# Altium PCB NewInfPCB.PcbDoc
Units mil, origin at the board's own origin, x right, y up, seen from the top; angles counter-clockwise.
Board outline 2952.76 x 3787.4 mil, 2 copper layers (Top Layer, Bottom Layer); 62 components, 64 nets, 265 pads, 41 vias.
Unrouted connection lines stored in the file: 1.
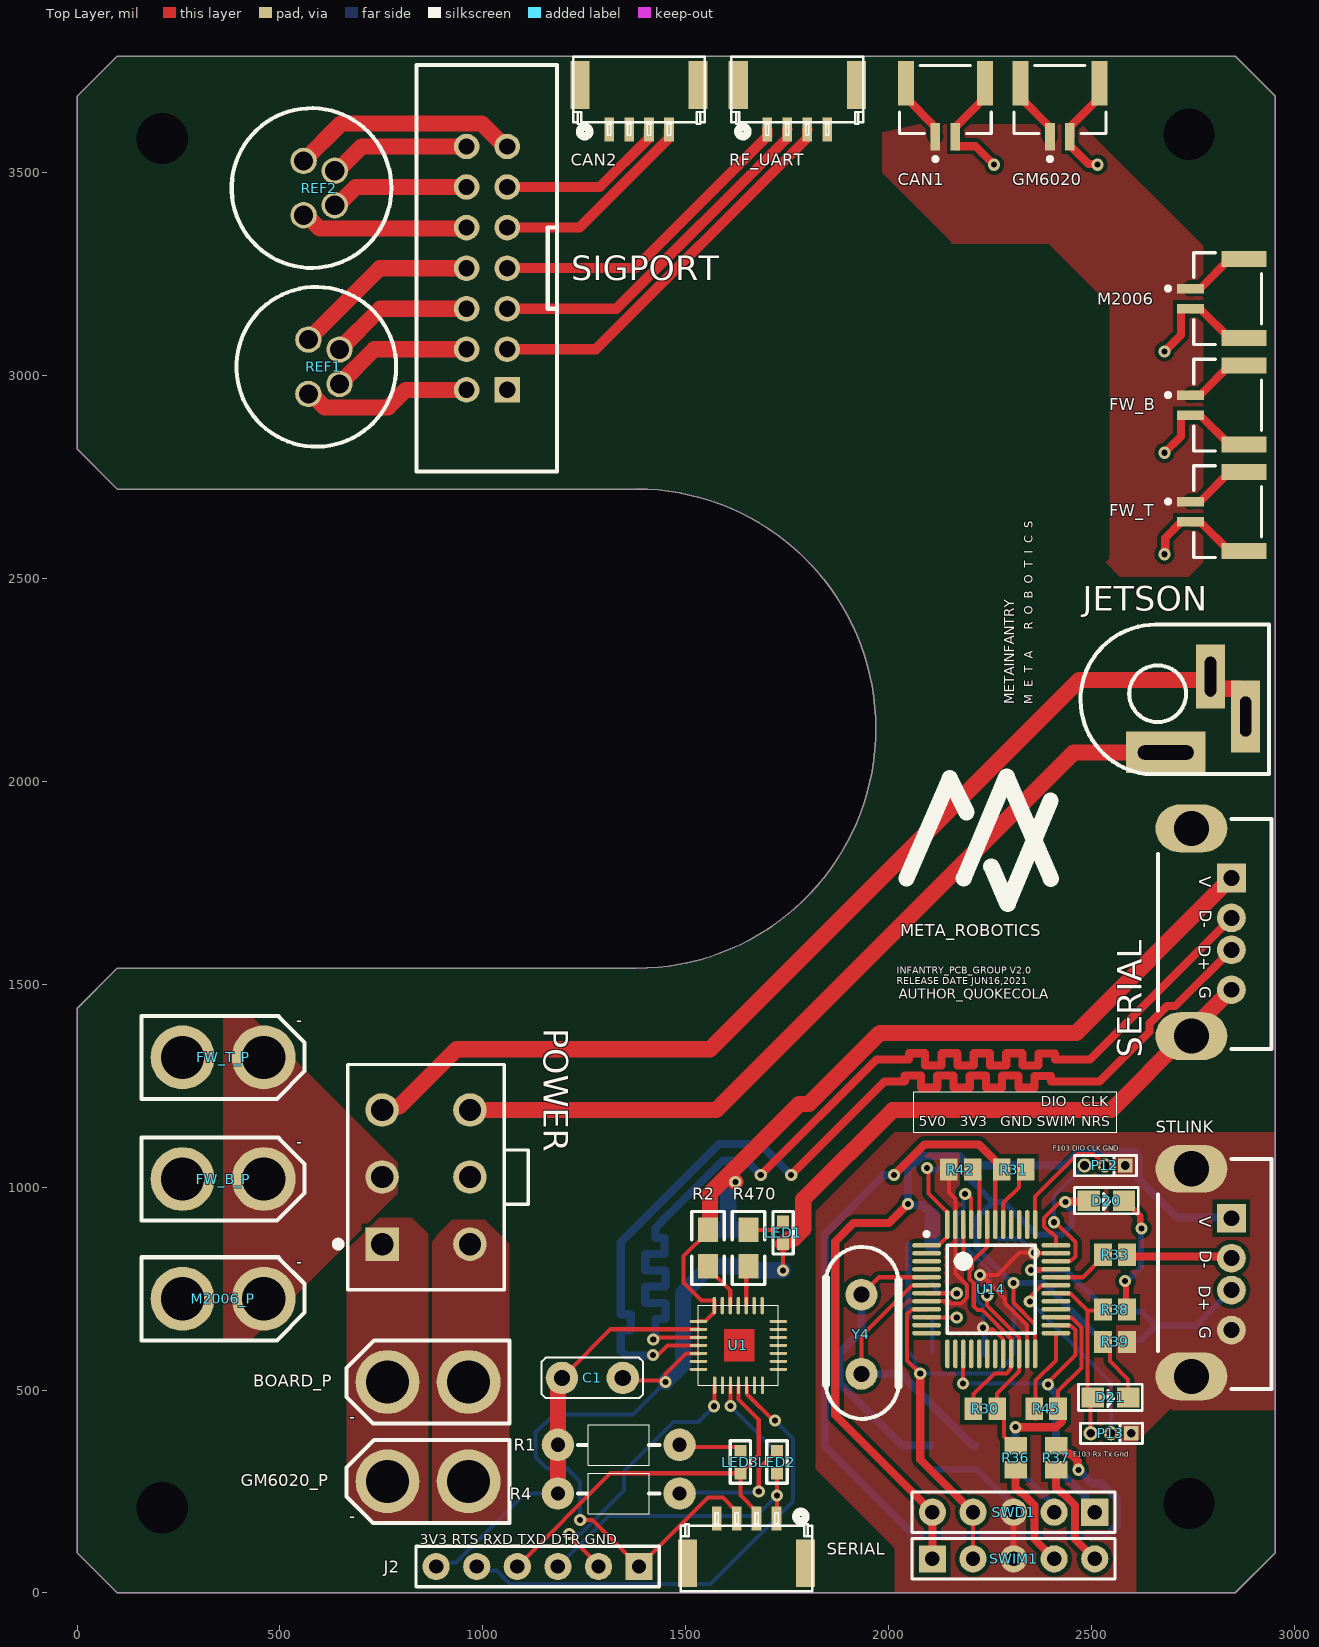
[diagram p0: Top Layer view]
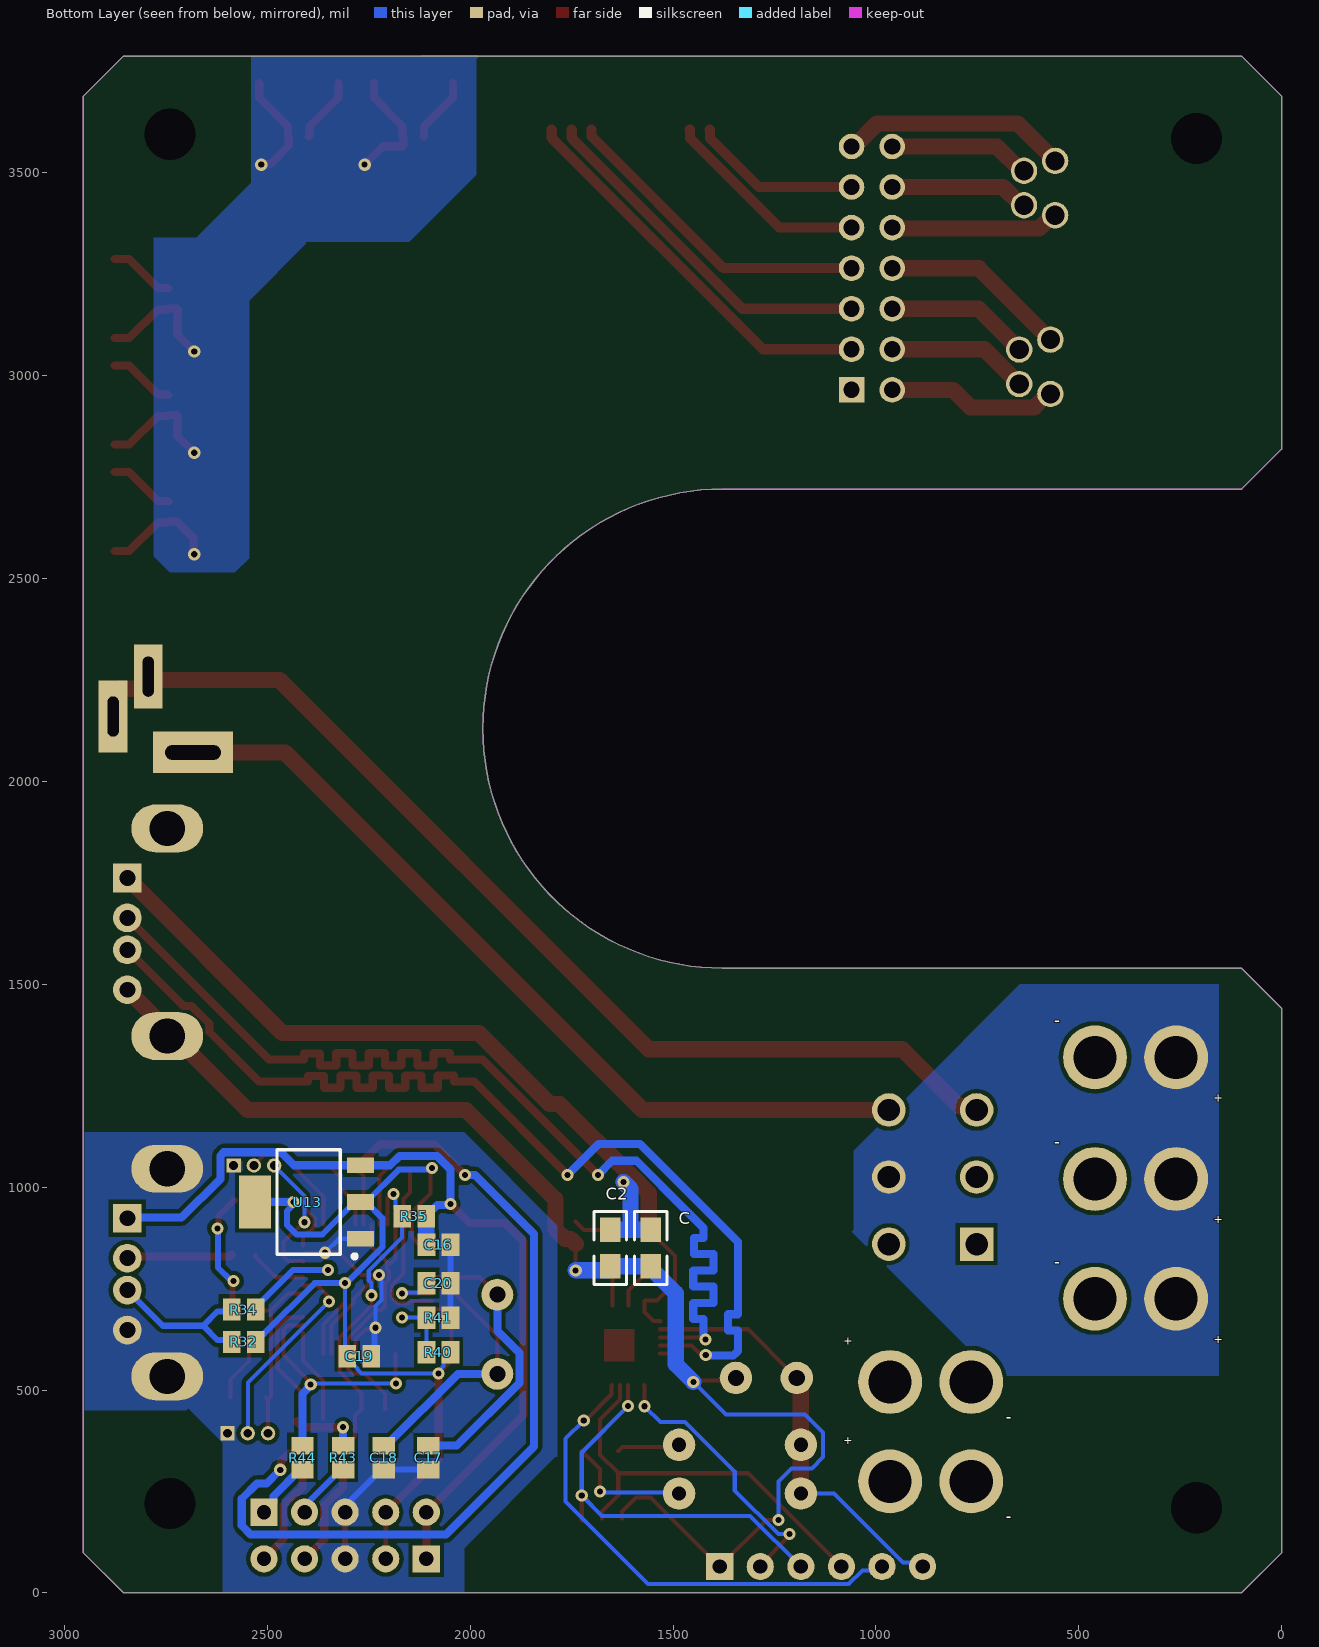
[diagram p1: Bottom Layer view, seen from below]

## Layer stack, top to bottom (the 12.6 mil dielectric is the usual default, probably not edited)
Top Solder: solder mask 0.4, Solder Resist, Dk 3.5
Top Layer: signal copper 1.4
Dielectric 1: dielectric 12.6, FR-4, Dk 4.8
Bottom Layer: signal copper 1.4
Bottom Solder: solder mask 0.4, Solder Resist, Dk 3.5

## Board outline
0.25,98.68 0.25,1441.19 98.68,1539.62 1378.2,1539.62 ccw(c1378.2,2130.17) 1378.2,2720.72 98.68,2720.72 0.25,2819.15 0.25,3689.23 98.68,3787.65 2854.58,3787.65 2953.01,3689.23 2953.01,98.68 2854.58,0.25 98.68,0.25

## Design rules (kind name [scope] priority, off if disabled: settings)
Clearance [All] p1: gap=10 ignorepadtopadclearanceinfootprint=FALSE except(0: Arc-Hole Track-Hole SMDPad-Text SMDPad-Hole THPad-Text THPad-Hole Via-Text Via-Hole Fill-Text Fill-Hole Poly-Text Poly-Hole Region-Text Region-Hole Text-Text Text-Hole; 5: Arc-Arc Arc-Track Arc-THPad Arc-Via Arc-Text Track-Track Track-THPad Track-Via Track-Text SMDPad-SMDPad SMDPad-THPad SMDPad-Via THPad-THPad THPad-Via Via-Via; 7.5: Arc-SMDPad Track-SMDPad)
PlaneConnect [All] p1: planeconnectstyle=Direct reliefexpansion=20 reliefentries=4 reliefconductorwidth=10 reliefairgap=10
PolygonConnect [All] p1: connectstyle=Direct reliefconductorwidth=10 reliefentries=4 polygonreliefangle="90 Angle" airgapwidth=10
RoutingVias [All] p1: holewidth=28 width=50 viastyle="Through Hole" minholewidth=28 minwidth=50 maxholewidth=28 maxwidth=50
SolderMaskExpansion [All] p1: expansion=4 istentingtop=FALSE
Width [All] p1: maxlimit=40 minlimit=10 preferedwidth=20 minimp=50.000000 maximp=50.000000 favimp=50.000000
29 further rules are at their usual default settings.

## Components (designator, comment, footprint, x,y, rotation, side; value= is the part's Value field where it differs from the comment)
BOARD_P "XT PLUGIN" XT30-M 865,520 r180 top
C "Cap" 0805 1555,895 r270 bottom value=0.1uF
C1 "4.7" 2P-150 1270,530 r0 top value=1uF
C2 "Cap" 0805 1655,895 r270 bottom value=1uF
C16 "Cap" C0805 2078.11,858.47 r0 bottom value=104
C17 "Cap" C0805 2103.11,333.46 r90 bottom value=22p
C18 "Cap" C0805 2213.11,333.46 r90 bottom value=22p
C19 "Cap" C0805 2273.11,583.47 r0 bottom value=104
C20 "Cap" C0805 2078.11,763.47 r0 bottom value=104
CAN1 "CAN1" JST-BM02B-GHS-TBT_V 2140,3655 r0 top
CAN2 "gh1.25_4p" GH1.25-LS-4P 1385,3705 r180 top
D20 "LED" 0805_LED 2533.11,963.47 r0 top
D21 "LED" 0805_LED 2543.11,478.46 r0 top
FW_B "CAN1" JST-BM02B-GHS-TBT_V 2810,2927.5 r270 top
FW_B_P "XT PLUGIN" XT30-M 360,1020 r0 top
FW_T "CAN1" JST-BM02B-GHS-TBT_V 2810,2665 r270 top
FW_T_P "XT PLUGIN" XT30-M 360,1320 r0 top
GM6020 "CAN1" JST-BM02B-GHS-TBT_V 2422.44,3655 r0 top
GM6020_P "XT PLUGIN" XT30-M 865,275 r180 top
J2 "" HDR2.54-LI-6P 1135,65 r180 top
JETSON "DC_PowerPort" DC-012 2683.15,2071.42 r90 top
LED1 "Res2" 0603 1740,860 r90 top value=1K
LED2 "Res2" 0603 1725,295 r90 top value=1K
LED3 "Res2" 0603 1635,295 r90 top value=1K
M2006 "CAN1" JST-BM02B-GHS-TBT_V 2810,3190 r270 top
M2006_P "XT PLUGIN" XT30-M 360,725 r0 top
P12 "ST-LINK" SIP3-1.27 2533.11,1053.46 r0 top
P13 "串口1" SIP3-1.27 2548.11,393.46 r0 top
POWER "64900621122" 64900621122 860,1025 r270 top
R1 "Res2" R 1335,365 r0 top value=1K
R2 "Res2" 0805 1555,895 r270 top value=1K
R4 "Res2" R 1335,245 r0 top value=1K
R30 "RES" C0805 2238.11,453.46 r0 top value=1k
R31 "RES" C0805 2308.11,1043.46 r180 top value=1k
R32 "RES" C0805 2558.11,618.47 r180 bottom value=1.5k
R33 "RES" C0805 2558.11,833.47 r180 top value=22
R34 "RES" C0805 2558.11,698.47 r180 bottom value=22
R35 "RES" C0805 2138.11,928.47 r0 bottom value=1.5k
R36 "RES" C0805 2313.11,332.99 r90 top value=22
R37 "RES" C0805 2413.11,333.46 r90 top value=22
R38 "RES" C0805 2558.11,698.47 r180 top value=1.5k
R39 "RES" C0805 2558.11,618.47 r180 top value=1.5k
R40 "RES" C0805 2078.11,593.47 r180 bottom value=4.7k
R41 "RES" C0805 2078.11,678.47 r0 bottom value=4.7k
R42 "RES" C0805 2178.11,1043.46 r0 top value=10k
R43 "RES" C0805 2313.11,333.46 r90 bottom value=22
R44 "RES" C0805 2413.11,333.46 r90 bottom value=22
R45 "RES" C0805 2388.11,453.46 r180 top value=100
R470 "Res2" 0805 1655,805 r90 top value=1K
REF1 "Referee_Air" "M8 CONNECTOR-LS" 589.68,3021.93 r270 top
REF2 "Referee_Air" "M8 CONNECTOR-LS" 577.91,3462.48 r270 top
RF_UART "gh1.25 P4" GH1.25-LS-4P 1775,3705 r180 top
SERIAL "gh1.25_4p" GH1.25-LS-4P 1650,85 r0 top
SERIAL "4 HEADER" USB-A/S_D 2845,1762.17 r270 top
SIGPORT "XH2.54 14PIN" DC-2.54-L-Z-14P 1010,3265 r90 top
STLINK "USB" USB-A/S_D 2845,923.43 r270 top
SWD1 "Head5" HDR2.54-LI-5P 2308.11,198.94 r180 top
SWIM1 "Header 5" HDR2.54-LI-5P 2308.11,83.94 r0 top
U1 "CP2102" CP2102 1630,610 r90 top
U13 "AMS1117-XX" SOT_223 2398.11,963.47 r90 bottom
U14 "STM32F103C8T6" LQFP48_N 2253.11,748.47 r0 top
Y4 "XTAL" XTAL_2 1934.48,624.92 r90 top

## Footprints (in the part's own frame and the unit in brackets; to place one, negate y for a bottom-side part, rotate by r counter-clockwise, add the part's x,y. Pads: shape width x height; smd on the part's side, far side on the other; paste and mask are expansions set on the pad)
2P-150 [mil]
  round 80 hole 40: 1(-75,0) 2(75,0)
  silkscreen extent -125,-50 125,50
0603 [mil]
  rect 30x30 smd: 1(0,0) 2(55,0)
  silkscreen extent -25,-25 80,25
0805 [mil]
  rect 60x50 smd: 1(0,0) 2(90,0)
  silkscreen extent -45,-40 135,40
0805_LED [mm]
  rect 1.4x1.27 smd: 1(-1.011,0.083) 2(1.199,0.083)
  silkscreen extent -1.9,-0.74 2.09,0.91
64900621122 [mm] "4.20mm Male Dual Row Vertical Header, 6p"
  rect 2.1x2.1 hole 1.4: 1(4.2,-2.75)
  round 2.1 hole 1.4: 2(0,-2.75) 3(-4.2,-2.75) 4(4.2,2.75) 5(0,2.75) 6(-4.2,2.75)
  silkscreen extent -7.05,-5.7 7.05,6.4, body extent -6.95,-4.8 7.25,6.3, height 12.82
C0805 [mm] "Chip Capacitor, Body 2.0x1.3mm, IPC High Density"
  rect 1.1x1.4 smd: 1(-0.75,0) 2(0.75,0)
  body extent -1.1,-0.72 1.1,0.72, height 1.4
CP2102 [mm]
  oval 0.2x1.1 smd: 1(-1.499,2.502) 2(-0.999,2.502) 3(-0.499,2.502) 4(0.001,2.502) 5(0.501,2.502) 6(1.001,2.502) 7(1.501,2.502) 15(1.499,-2.502) 16(0.999,-2.502) 17(0.499,-2.502) 18(-0.001,-2.502) 19(-0.501,-2.502) 20(-1.001,-2.502) 21(-1.501,-2.502)
  oval 1.1x0.2 smd: 8(2.489,1.511) 9(2.489,1.011) 10(2.489,0.511) 11(2.489,0.011) 12(2.489,-0.489) 13(2.489,-0.989) 14(2.489,-1.489) 22(-2.489,-1.511) 23(-2.489,-1.011) 24(-2.489,-0.511) 25(-2.489,-0.011) 26(-2.489,0.489) 27(-2.489,0.989) 28(-2.489,1.489)
  Top Layer region: -1.016,-1.016 1.016,-1.016 1.016,0.889 -1.016,0.889
  silkscreen extent -2.5,-2.5 2.5,2.5
DC-2.54-L-Z-14P [mm] "立式直插简牛插座，间距2.54 淘宝ID:黄晶宝石   店铺网址:https://shop463601444.taobao.com"
  rect 1.6x1.6 hole 1.02: 1(-7.62,-1.27)
  round 1.6 hole 1.02: 2(-7.62,1.27) 3(-5.08,-1.27) 4(-5.08,1.27) 5(-2.54,-1.27) 6(-2.54,1.27) 7(0,-1.27) 8(0,1.27) 9(2.54,-1.27) 10(2.54,1.27) 11(5.08,-1.27) 12(5.08,1.27) 13(7.62,-1.27) 14(7.62,1.27)
  silkscreen extent -12.72,-4.4 12.72,4.4, body extent -12.72,-4.4 12.71,4.7, height 8.8
DC-012 [mm] "5.5*2.1                  淘宝ID:黄晶宝石"
  rect 2.6x5 hole 0.9 slot 3.5 at 90 deg: 1(0,0)
  rect 4.5x1.8 hole 0.7 slot 2.5 at 0 deg: 2(2.25,-5)
  rect 4x1.8 hole 0.7 slot 2.5 at 0 deg: 3(4.75,-2.8)
  silkscreen extent -1.35,-6.48 8,5.33, body extent -1.11,-6.47 7.89,4.53, height 13.6
GH1.25-LS-4P [mm] "A1257WR-S-4P"
  rect 1.2x3 smd: 0(-3.7,-0.3) 0(3.7,-0.3)
  rect 0.6x1.5 smd: 1(1.875,2.5) 2(0.625,2.5) 3(-0.625,2.5) 4(-1.875,2.5)
  silkscreen extent -4.13,-2.05 4.12,2.93, body extent -4.12,-2.15 4.12,2.25, height 4.2
HDR2.54-LI-5P [mm] "排针，5脚"
  rect 1.7x1.7 hole 0.9: 1(-5.08,0)
  round 1.7 hole 0.9: 2(-2.54,0) 3(0,0) 4(2.54,0) 5(5.08,0)
  silkscreen extent -6.35,-1.27 6.35,1.27, body extent -6.35,-1.27 6.35,1.27, height 8.5
HDR2.54-LI-6P [mm] "排针，6脚"
  rect 1.7x1.7 hole 0.9: 1(-6.35,0)
  round 1.7 hole 0.9: 2(-3.81,0) 3(-1.27,0) 4(1.27,0) 5(3.81,0) 6(6.35,0)
  silkscreen extent -7.62,-1.27 7.62,1.27, body extent -7.62,-1.27 7.62,1.27, height 8.5
JST-BM02B-GHS-TBT_V [mm] "Connector, 2-Leads, Body 5.75x4.25mm, Pitch 1.25mm"
  rect 0.6x1.7 smd: 1(-0.625,-1.675) 2(0.625,-1.675)
  rect 1x2.8 smd: MP1(-2.475,1.675) MP2(2.475,1.675)
  silkscreen extent -2.88,-3.2 2.88,2.78, body extent -2.88,-2.17 2.87,2.78, height 4.21
LQFP48_N [mm] "Thin QFP, 48-Leads, Body 7x7mm, Pitch 0.5mm, IPC Medium Density"
  oval 1.8x0.3 smd: 1(-4.05,2.75) 2(-4.05,2.25) 3(-4.05,1.75) 4(-4.05,1.25) 5(-4.05,0.75) 6(-4.05,0.25) 7(-4.05,-0.25) 8(-4.05,-0.75) 9(-4.05,-1.25) 10(-4.05,-1.75) 11(-4.05,-2.25) 12(-4.05,-2.75) 25(4.05,-2.75) 26(4.05,-2.25) 27(4.05,-1.75) 28(4.05,-1.25) 29(4.05,-0.75) 30(4.05,-0.25) 31(4.05,0.25) 32(4.05,0.75) 33(4.05,1.25) 34(4.05,1.75) 35(4.05,2.25) 36(4.05,2.75)
  oval 0.3x1.8 smd: 13(-2.75,-4.05) 14(-2.25,-4.05) 15(-1.75,-4.05) 16(-1.25,-4.05) 17(-0.75,-4.05) 18(-0.25,-4.05) 19(0.25,-4.05) 20(0.75,-4.05) 21(1.25,-4.05) 22(1.75,-4.05) 23(2.25,-4.05) 24(2.75,-4.05) 37(2.75,4.05) 38(2.25,4.05) 39(1.75,4.05) 40(1.25,4.05) 41(0.75,4.05) 42(0.25,4.05) 43(-0.25,4.05) 44(-0.75,4.05) 45(-1.25,4.05) 46(-1.75,4.05) 47(-2.25,4.05) 48(-2.75,4.05)
  silkscreen extent -4.17,-2.75 2.75,3.57, body extent -3.5,-3.5 3.5,3.5, height 1.6
"M8 CONNECTOR-LS" [mm]
  round 1.65 hole 1.2: 0(-1.08,1.45) 1(1.08,1.45) 2(-1.7,-0.5) 3(1.7,-0.5)
  silkscreen extent -5,-5 5,5, body extent 0,0 0,0, height 19.1
R [mil]
  round 80 hole 35: 1(-150,0) 2(150,0)
  silkscreen extent -100,-50 100,50
SIP3-1.27 [mm]
  rect 0.9x0.9 hole 0.55: 1(1.27,0)
  round 0.9 hole 0.55: 2(0,0) 3(-1.27,0)
  silkscreen extent -1.91,-0.64 1.97,0.64
SOT_223 [mm]
  rect 1x1.7 smd: 1(-2.3,-3.25) 2(0,-3.25) 3(2.3,-3.25)
  rect 3.3x2 smd: 2(0,3.349)
  silkscreen extent -3.53,-3 3.28,1.98, body extent -3.25,-3.51 3.25,3.51, height 1.93
USB-A/S_D [mm] "A型直插母头，"
  oval 3x4.5 hole 2.2: 1(-3.1,-2.5) 1(9.9,-2.5)
  round 1.8 hole 1: 1(7,0) 2(4.5,0) 3(2.5,0)
  rect 1.8x1.8 hole 1: 4(0,0)
  silkscreen extent -3.7,-4.6 10.7,2.5, body extent -3.71,-4.6 10.69,2.5, height 14
XT30-M [mm]
  round 4 hole 2.7: 1(-2.54,0) 2(2.54,0)
  silkscreen extent -5.1,-2.6 5.11,2.6, body extent -5.18,-2.8 5.02,2.8, height 10.66
XTAL_2 [mm]
  round 2 hole 1: 1(-2.157,0.035) 2(2.796,0.035)
  silkscreen extent -4.98,-2.3 5.79,2.27, body extent -5.29,-2.36 6.06,2.29, height 3.5

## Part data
C C2: "Capacitor"
C1: library part "Cap Pol1", "Polarized Capacitor (Radial)"
CAN1 FW_B FW_T GM6020 M2006: library part CMP-2000-05957-1, "Disconnectable Crimp Style Connector, Pitch 1.25 mm, 1 x 2 Position, Height 4.05 mm, -25 to 85 degC, RoHS, Tape and Reel", Color=Natural, Manufacturer=JST-Sales-America-Inc., Package Description="Disconnectable Crimp Style Connector, Pitch 1.25 mm, 1 x 2 Position, Height 4.05 mm", Package Reference=BM02B-GHS-TBT
J2: library part CON6, "Connector"
LED1 LED2 LED3 R1 R2 R4 R470: "Resistor"
P12 P13: library part "Header 3", "Header, 3-Pin"
POWER: library part CMP-1502-00495-1, "THT Male Header WR-MPC4, Vertical, Dual Row, pitch 4.2 mm, 6 pins", Contact Resistance=10mOhm, Manufacturer="Wurth Elektronik", Operating Temperature=-40to105degC, Working Voltage=600VAC
SERIAL: "4 Pin Header"
STLINK: library part USB_G
SWD1: library part "HEAD 5"
SWIM1: "Header, 5-Pin"
U1: library part Component_2
U13: "AMS   800mA LOW DROPOUT VOLTAGE REGULATOR"
U14: "STM32 ARM-based 32-bit MCU with 64 Kbytes Flash, 48-pin LQFP, Industrial Temperature"

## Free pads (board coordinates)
  round 0 hole 125.98: ""(210,210) ""(210,3585) ""(2740,220) ""(2740,3595)

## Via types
v1: diameter 30, hole 15, Top Layer to Bottom Layer, 41 vias

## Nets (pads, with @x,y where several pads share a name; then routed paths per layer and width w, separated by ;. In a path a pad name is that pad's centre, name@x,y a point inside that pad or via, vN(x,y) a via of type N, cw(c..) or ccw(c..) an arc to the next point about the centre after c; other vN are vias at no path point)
3.3: C1.1 J2.6 R1.1 R4.1 U1.6 | length 1061.8
  Top Layer w10: C1.1@1185,540 1205,540 1314.87,649.87 1531.06,649.87 U1.6
  Top Layer w40: R4.1 R1.1 C1.1@1185,540
  Bottom Layer w10: J2.6 894.93,74.93 933.46,74.93 1103.53,245 R4.1
3V3: C19.2 D20.1 R32.2 R40.2 SWD1.4 SWIM1.2 U13.2 U14.1 U14.9 U14.24 U14.36 U14.48 | length 3006.1
  Top Layer w10: v1(2078.11,540.75) 2045.73,573.13 2045.73,687.19 2057.44,698.91 2093.31,698.91 U14.9 ; U14.1 2123.19,856.73 2144.84,878.39 U14.48 2144.84,937.44 2098.11,984.17 2098.11,1043.46 v1(2094.39,1047.18) ; SWIM1.2 SWD1.4 ; v1(2308.11,763.47) 2308.11,715.18 2361.37,661.91 U14.24 ; U14.36 2412.55,877.64 2401.73,888.47 2397.75,888.47 2383.11,903.11 2383.11,923.82 2418.92,959.64 2431.78,959.64 v1(2435.61,963.47)
  Top Layer w20: v1(2078.11,540.75) 2078.11,328.94 SWD1.4 ; v1(2435.61,963.47) 2437.24,965.1 2491.66,965.1 D20.1
  Bottom Layer w10: R40.2 2065.23,576.81 2065.23,559.03 2078.11,546.16 v1(2078.11,540.75) 2267.75,540.75 2277.73,550.73 2277.73,552.66 2302.63,577.56 C19.2 2308.11,588.94 v1(2308.11,763.47)
  Bottom Layer w15: v1(2094.39,1047.18) 2098.11,1043.46 2176.38,1043.46 U13.2@2256.38,963.47 ; v1(2435.61,963.47) 2435.61,956.91 2451.89,940.62 2451.89,907.25 2428.11,883.47 2363.93,883.47 2283.93,963.47 2270.15,963.47 U13.2@2256.38,963.47 ; R32.2 2528.58,624.37 2514.43,638.52 2508.52,638.52 2383.58,763.47 v1(2308.11,763.47) 2305.24,763.47 2216.38,852.33 2216.38,923.47 U13.2@2256.38,963.47
  Bottom Layer w20: v1(2435.61,963.47) U13.2@2529.95,963.47
5V0: C16.2 R35.1 STLINK.4 SWD1.5 SWIM1.1 U13.3 | length 2265.8
  Top Layer w20: v1(2048.11,958.47) 2000.91,911.27 1914.02,911.27 1868.74,865.99 1868.74,438.31 SWD1.5 SWIM1.1
  Bottom Layer w20: R35.1 2108.58,934.37 2096.93,946.02 2091.02,946.02 2080.49,956.55 2050.02,956.55 v1(2048.11,958.47) 2048.11,1043.32 2081.97,1077.18 2174.48,1077.18 2197.64,1054.02 U13.3 2434.25,1054.02 2466.41,1086.18 2608.11,1086.18 2608.11,1085.11 2615.82,1077.39 2615.82,1020.36 2711.18,925 2843.43,925 STLINK.4
  Bottom Layer w40: C16.2 2108.11,858.94 2108.11,927.99 R35.1
(NRS): R37.1 SWIM1.5 | length 261.3
  Top Layer w20: R37.1 2413.11,259.12 2424.82,247.4 2428.18,247.4 2459.64,215.94 2459.64,132.4 SWIM1.5
(SWCLK): R44.1 SWD1.1 | length 147.8
  Bottom Layer w20: R44.1 2419.01,303.94 2484.64,238.31 2484.64,222.4 SWD1.1
(SWDIO): R43.1 SWD1.2 | length 147.8
  Bottom Layer w15: R43.1 2319.01,303.94 2398.17,224.78 2398.17,208.87 SWD1.2
(SWIM): R36.1 SWIM1.4 | length 260.8
  Top Layer w20: R36.1 2313.11,259.12 2324.82,247.4 2328.18,247.4 2359.64,215.94 2359.64,132.4 SWIM1.4
AMMO_DC: FW_B_P.1 FW_T_P.1 M2006_P.1 POWER.5
AMMO_GND: FW_B_P.2 FW_T_P.2 M2006_P.2 POWER.2
BOOT0: R42.2 U14.44 | length 142.2
  Top Layer w10: R42.2 2223.58,1027.52 U14.44
CAN1_H: CAN1.2 CAN1.MP2 FW_B.2 FW_B.MP2 FW_T.2 FW_T.MP2 GM6020.2 GM6020.MP2 M2006.2 M2006.MP2 | length 1452.5
  Top Layer w20: CAN1.MP2 2237.44,3685.51 2166.42,3614.49 2166.42,3590.87 CAN1.2 2164.61,3567.4 2166.42,3565.59 2214.41,3565.59 v1(2260,3520) ; v1(2515,3520) 2513.09,3521.91 2492.54,3521.91 2447.05,3567.4 GM6020.2 2448.86,3590.87 2448.86,3614.49 2519.88,3685.51 GM6020.MP2 ; v1(2680,2560) 2681.91,2561.91 2681.91,2599.91 2722.4,2640.39 FW_T.2 2745.87,2638.58 2769.49,2638.58 2840.51,2567.56 FW_T.MP2 ; v1(2680,2810) 2720.59,2850.59 2720.59,2901.08 2722.4,2902.89 FW_B.2 2745.87,2901.08 2769.49,2901.08 2840.51,2830.06 FW_B.MP2 ; v1(2680,3060) 2720.59,3100.59 2720.59,3163.58 2722.4,3165.39 M2006.2 2745.87,3163.58 2769.49,3163.58 2840.51,3092.56 M2006.MP2
CAN1_L: CAN1.1 CAN1.MP1 FW_B.1 FW_B.MP1 FW_T.1 FW_T.MP1 GM6020.1 GM6020.MP1 M2006.1 M2006.MP1 | length 810.3
  Top Layer w20: CAN1.MP1 2042.56,3685.51 2113.58,3614.49 2113.58,3590.87 CAN1.1 ; GM6020.MP1 2325,3685.51 2396.02,3614.49 2396.02,3590.87 GM6020.1 ; FW_T.1 2745.87,2691.42 2769.49,2691.42 2840.51,2762.44 FW_T.MP1 ; FW_B.1 2745.87,2953.92 2769.49,2953.92 2840.51,3024.94 FW_B.MP1 ; M2006.1 2745.87,3216.42 2769.49,3216.42 2840.51,3287.44 M2006.MP1
CAN2_H: CAN2.3 SIGPORT.11 | length 420.2
  Top Layer w25: SIGPORT.11 1288.44,3465 1408.92,3585.48 1408.92,3605.89 CAN2.3
CAN2_L: CAN2.4 SIGPORT.9 | length 510.8
  Top Layer w25: SIGPORT.9 1237.65,3365 1458.13,3585.48 1458.13,3605.89 CAN2.4
D+: SERIAL.2@2845,1585 U1.4 | length 2672.4
  Top Layer w10: v1(1419.31,586.16) 1423.84,586.16 1425,585 1430,585 1455.06,610.06 U1.4
  Top Layer w20: v1(1760,1030) 1990,1260 2030,1260 2040,1260 2040,1275 2080,1275 2080,1245 2120,1245 2120,1275 2160,1275 2160,1245 2200,1245 2200,1275 2240,1275 2240,1245 2280,1245 2280,1275 2320,1275 2320,1245 2360,1245 2360,1274.09 2400,1274.09 2400,1260 2520,1260 2540,1280 2642.99,1382.99 2642.99,1403.08 2686.37,1446.46 2706.46,1446.46 SERIAL.2@2845,1585
  Bottom Layer w20: v1(1419.31,586.16) 1419.31,585 1351.72,585 1345,591.72 1340,596.72 1340,646.72 1364.52,646.72 1364.52,686.72 1340,686.72 1340,865 1355,880 1581.72,1106.72 1683.28,1106.72 v1(1760,1030)
D-: SERIAL.3@2845,1663.74 U1.5 | length 2672.9
  Top Layer w10: v1(1420.11,624.87) 1425.28,624.87 1430.15,629.74 U1.5
  Top Layer w20: v1(1685,1030) 1970,1315 2040,1315 2050,1315 2050,1330 2090,1330 2090,1300 2130,1300 2130,1330 2170,1330 2170,1300 2210,1300 2210,1330 2250,1330 2250,1300 2290,1300 2290,1330 2330,1330 2330,1300 2370,1300 2370,1329.34 2410,1329.34 2410,1315 2490,1315 2496.26,1315 SERIAL.3@2845,1663.74
  Bottom Layer w20: v1(1420.11,624.87) 1425.28,624.87 1425.28,674.87 1450.28,674.87 1450.28,714.87 1400.28,714.87 1400.28,754.87 1450.28,754.87 1450.28,794.87 1400.28,794.87 1400.28,834.87 1448.06,834.87 1448.06,874.87 1425.28,874.87 1425.28,899.78 1455.5,930 1470.5,945 1590.5,1065 1650,1065 v1(1685,1030)
DTR: J2.2 U1.28 | length 676.9
  Top Layer w10: v1(1212.98,145) 1212.98,141.01 1285,68.99 J2.2 ; v1(1570,460) 1570.69,460.69 1570.69,511.31 U1.28
  Bottom Layer w10: v1(1212.98,145) 1240.36,145 1347.97,252.62 1347.97,298.68 1470.23,420.94 1530.94,420.94 v1(1570,460)
GMB_DC: BOARD_P.1 GM6020_P.1 POWER.4
GMB_GND: BOARD_P.2 GM6020_P.2 POWER.1
GND: C1.2 C2.2 C.2 J2.1 LED1.1 SERIAL.1@2746.57,1372.4 SERIAL.1@2746.57,1884.21 SERIAL.1@2845,1486.57 SERIAL.3@1625.39,183.43 U1.3 | length 3421.3
  Top Layer w10: v1(1240,180) 1270,180 J2.1 1555,235 1591.54,235 1625.39,201.14 SERIAL.3@1625.39,183.43 ; C1.2 1351.17,523.83 1446.17,523.83 v1(1450,520) 1450,539.23 1500.96,590.19 1531.32,590.19 U1.3 ; v1(1740,795) LED1.1
  Top Layer w40: LED1.1 1752.5,872.5 1766.39,872.5 1790,896.11 1790,970 2010,1190 2548.43,1190 2734.02,1375.59 SERIAL.1@2845,1486.57
  Bottom Layer w10: v1(1240,180) 1240,275 1208.09,306.91 1158.09,306.91 1130,335 1130,395 1175,440 1370,440 v1(1450,520)
  Bottom Layer w40: v1(1450,520) 1493.43,563.43 1493.43,738.43 1555,800 C.2 C2.2 1655,800 1660,795 v1(1740,795)
GNDG: C16.1 C17.1 C18.1 C19.1 C20.1 P12.1 P13.1 R39.1 R41.1 R42.1 STLINK.1 SWD1.3 SWIM1.3 U13.1 U14.8 U14.20 U14.23 U14.35 U14.47 | length 1859.5
  Top Layer w10: U14.8 2148.33,718.94 2153.81,713.47 2178.46,713.47 2193.11,728.11 2193.11,758.79 2164.52,787.37 U14.47 2164.52,971.45 2148.58,987.39 R42.1 ; v1(2225,783.47) v1@2228.46,783.47 ; v1(2233.11,653.47) 2236.93,649.64 2257.88,649.64 2282.29,625.23 2282.29,589.36 U14.20 ; U14.23 2341.69,660.38 2287.48,714.6 2287.48,724.45 v1@2228.46,783.47 ; U14.35 2412.21,837.39 2359.18,837.39 v1(2358.11,838.47) 2323.11,838.47 2268.11,783.47 v1@2228.46,783.47
  Top Layer w15: SWIM1.3 SWD1.3
  Bottom Layer w10: v1(2225,783.47) 2225,778.05 2218.11,771.16 2218.11,722.52 2233.11,707.52 v1(2233.11,653.47) ; U13.1 2323.66,872.91 v1(2358.11,838.47)
  Bottom Layer w15: R41.1 C20.1 C16.1 ; C17.1 C18.1 2219.01,303.94 2298.17,224.78 2298.17,208.87 SWD1.3 ; v1(2233.11,653.47) 2235.98,650.6 2235.98,591.07 C19.1
MPC_DC: JETSON.1 POWER.6 | length 2079.8
  Top Layer w40: POWER.6 1575.35,1190.35 2456.42,2071.42 JETSON.1
MPC_GND: JETSON.2 JETSON.3 POWER.3 | length 2635.6
  Top Layer w40: POWER.3 759.9,1198.52 793.52,1198.52 935,1340 1560,1340 2470,2250 2784.96,2250 2806.38,2228.58 2864.57,2228.58 2880,2213.15 JETSON.2
NetC20_2: C20.2 U14.7 | length 148.8
  Top Layer w10: U14.7 2093.74,738.54 2168.03,738.54 v1(2168.11,738.47)
  Bottom Layer w10: C20.2 2107.63,757.56 2124.29,740.91 2165.67,740.91 v1(2168.11,738.47)
NetD20_2: D20.2 R38.1 | length 328.4
  Top Layer w15: D20.2@2582.04,968.47 D20.2 2582.86,966.73 2620.24,929.35 2620.24,901.34 v1(2623.11,898.47) ; v1(2583.11,768.47) 2585.37,766.2 2585.37,700.73 R38.1 2592.63,693.47 R38.1@2602.63,703.47
  Bottom Layer w15: v1@2588.11,768.47 2621.67,802.03 v1@2621.67,899.9
NetD21_2: D21.2 R39.2 | length 162.3
  Top Layer w10: R39.2 2545.23,601.81 2545.23,571.35 2590.3,526.28 D21.2
NetLED1_2: LED1.2 R470.2 | length 93.3
  Top Layer w10: R470.2 1720,895 LED1.2
NetLED2_2: LED2.2 R4.2 | length 315.7
  Top Layer w10: v1(1680,250) 1680,305 LED2.2
  Bottom Layer w10: R4.2 1487.5,247.5 1677.5,247.5 v1(1680,250)
NetLED3_2: LED3.2 R1.2 | length 156.2
  Top Layer w10: R1.2 1490,360 1625,360 LED3.2
NetR2_2: R2.2 U1.10 | length 119.7
  Top Layer w10: R2.2 1555,800 1609.87,745.13 U1.10
NetR32_1: R32.1 R34.1 STLINK.2 | length 383.5
  Bottom Layer w15: R32.1@2592.53,623.36 2623,623.36 2658.11,658.47 ; R34.1@2592.53,693.57 2623,693.57 2658.11,658.47 ; STLINK.2 2757.21,658.47 2658.11,658.47
NetR33_1: R33.1 STLINK.3 | length 260.9
  Top Layer w20: R33.1 2591.87,829.23 2840.77,829.23 STLINK.3
NetR40_1: R40.1 R41.2 U14.10 | length 220.4
  Top Layer w10: U14.10 2094.01,679.22 2167.35,679.22 v1(2168.11,678.47)
  Bottom Layer w10: R40.1 R41.2 v1(2168.11,678.47)
OS_IN: C17.2 U14.5 Y4.2 | length 706.8
  Top Layer w10: Y4.2 1976.1,777.99 U14.5
  Bottom Layer w20: Y4.2 1933.11,645.48 1878.74,591.11 1878.74,517.48 2033.22,362.99 C17.2
OS_OUT: C18.2 U14.6 Y4.1 | length 659.1
  Top Layer w10: Y4.1 1933.11,633.63 2057.44,757.96 2093.31,757.96 U14.6
  Bottom Layer w20: Y4.1 2030.19,540 2207.2,362.99 C18.2
REFEREE_A1: REF1.0 SIGPORT.6 | length 354.9
  Top Layer w40: REF1.0 747.32,3165 SIGPORT.6
REFEREE_A2: REF1.1 SIGPORT.4 | length 348.7
  Top Layer w40: REF1.1 732.36,3065 SIGPORT.4
REFEREE_A3: REF1.2 SIGPORT.8 | length 463
  Top Layer w40: REF1.2 746.14,3265 SIGPORT.8
REFEREE_A4: REF1.3 SIGPORT.2 | length 421.5
  Top Layer w40: REF1.3 576.75,2955 609.83,2921.93 766.83,2921.93 809.91,2965 SIGPORT.2
REFEREE_B1: REF2.0 SIGPORT.14 | length 349.9
  Top Layer w40: REF2.0 641.75,3505 701.75,3565 SIGPORT.14
REFEREE_B2: REF2.1 SIGPORT.12 | length 343.7
  Top Layer w40: REF2.1 641.75,3419.96 686.79,3465 SIGPORT.12
REFEREE_B3: REF2.2 SIGPORT.13 | length 563.3
  Top Layer w40: REF2.2 650.32,3621.5 997.28,3621.5 1053.78,3565 SIGPORT.13
REFEREE_B4: REF2.3 SIGPORT.10 | length 416.5
  Top Layer w40: REF2.3 564.98,3395.55 598.05,3362.48 957.48,3362.48 SIGPORT.10
RTS: J2.5 U1.24 | length 1219.3
  Top Layer w10: U1.24 1651.19,510.94 1651.19,489.66 1715.85,425 v1(1720,425)
  Bottom Layer w10: J2.5 994.93,55.07 1033.46,55.07 1067,21.54 1561.54,21.54 1765,225 1765,380 v1(1720,425)
RX: D21.1 P13.3 R38.2 U14.30 | length 437.7
  Top Layer w10: U14.30 2412.9,738.28 2448.77,738.28 2490.49,696.56 ; D21.1@2490.49,483.46 2490.49,696.56 ; P13.3 2498.11,476.54 D21.1 ; R38.2 2526.67,696.56 2490.49,696.56
RXD: J2.4 LED3.1 SERIAL.2@1674.61,183.43 U1.25 | length 1029.4
  Top Layer w10: J2.4 1315,295 LED3.1 ; U1.25 1630.44,476.43 1680,426.87 1680,340 LED3.1 ; SERIAL.2@1674.61,183.43 1674.61,201.14 1635,240.75 LED3.1
SUS: R470.1 U1.12 | length 99.4
  Top Layer w10: U1.12 1649.24,799.24 R470.1
SWCLK1: P12.2 U14.37 | length 295.3
  Top Layer w10: U14.37 2361.37,976.73 2465.82,1081.18 2505.39,1081.18 P12.2
SWDIO1: P12.3 U14.34 | length 331.7
  Top Layer w10: v1(2408.11,913.47) 2411.38,913.47 2460.49,864.36 2460.49,829.42 2448.77,817.71 2412.9,817.71 U14.34
  Bottom Layer w10: v1(2408.11,913.47) 2408.11,978.47 P12.3
SWIM: R30.2 R35.2 R36.2 U14.22 U14.45 | length 828.5
  Top Layer w10: v1(2188.88,983.47) 2193.11,983.47 2203.55,973.02 2203.55,908.26 U14.45 ; v1(2243.11,733.47) 2243.11,708.47 2321.66,629.91 2321.66,589.36 U14.22 2322,545.5 2267.63,491.13 R30.2 2284.29,436.81 2284.29,385.43 2307.2,362.52 R36.2
  Bottom Layer w10: v1(2188.88,983.47) 2188.88,978.05 2184.29,973.47 2184.29,945.12 R35.2 2167.63,876.19 2250,793.82 2250,769.8 2243.67,763.47 2243.67,734.03 v1(2243.11,733.47)
SWIM_IN: R30.1 U14.21 U14.43 U14.46 | length 691.6
  Top Layer w10: U14.46 2184.21,823.99 2197.49,810.71 2200,810.71 2205,815.71 ; R30.1 2209.81,454.69 2209.81,490.17 2260.73,541.08 2290.26,541.08 2301.04,551.87 2301.04,557.72 2302.32,559 2302.32,619.03 2303.6,620.32 2303.6,625.14 2231.7,697.03 2219.18,697.03 2210,706.22 2210,763.11 2200,773.11 2200,793.82 2205,798.82 2205,815.71 ; U14.43 2243.26,853.98 2205,815.71
SWIM_RST: R31.2 R37.2 U14.42 | length 2322.6
  Top Layer w10: U14.42 2262.95,1027.84 R31.2
  Top Layer w20: v1(2013.11,1030) 2088.11,1105 2222.95,1105 2278.58,1049.37 R31.2 ; R37.2 2419.01,362.99 2438.91,343.09 2447.91,343.09 2466.19,324.81 2466.19,305.38 v1(2468.11,303.46)
  Bottom Layer w20: v1(2013.11,1030) 1988.11,1030 1843.11,885 1843.11,360.65 2059.82,143.94 2541.25,143.94 2563.11,165.79 2563.11,232.08 2525.1,270.08 2501.49,270.08 v1(2468.11,303.46)
SWIM_RST_IN: R31.1 U14.41 | length 158.3
  Top Layer w10: U14.41 2282.63,960.42 2320.98,998.76 2320.98,1026.81 R31.1
T_JTCK: R44.2 U14.15 U14.26 | length 658.8
  Top Layer w10: v1(2183.11,515.75) 2183.11,518.47 2183.86,519.22 2183.86,588.67 U14.15 ; v1(2393.11,513.47) 2393.11,518.47 2460.49,585.85 2460.49,647.82 2448.77,659.54 2412.9,659.54 U14.26
  Bottom Layer w10: v1(2183.11,515.75) 2183.33,515.97 2390.61,515.97 v1(2393.11,513.47)
  Bottom Layer w20: v1(2393.11,513.47) 2393.11,510.76 2413.11,490.76 R44.2
T_JTMS: R43.2 R45.1 U14.27 | length 464.2
  Top Layer w10: U14.27 2412.9,679.22 2450.3,679.22 2475.49,654.03 2475.49,554.63 2418.11,497.25 R45.1@2418.11,453.46
  Top Layer w20: v1(2313.11,408.46) 2313.17,408.41 2413.05,408.41 2427.16,422.52 2427.16,423.46
  Bottom Layer w20: R43.2 v1(2313.11,408.46)
T_SWDIO_IN: R45.2 U14.25 | length 231.9
  Top Layer w10: R45.2@2362.55,429.02 2362.55,523.27 2412.55,573.27 U14.25
TX: P13.2 U14.31 | length 495.4
  Top Layer w10: v1(2348.11,718.47) 2351.93,722.29 2351.93,733.56 2376.34,757.96 2412.21,757.96 U14.31
  Bottom Layer w10: v1(2348.11,718.47) 2548.11,518.47 P13.2
TXD: J2.3 LED2.1 SERIAL.1@1723.82,183.43 U1.26 | length 1048.5
  Top Layer w10: v1(1610.76,460.76) U1.26 ; SERIAL.1@1723.82,178.78 1725,179.96 v1(1725,240) LED2.1
  Bottom Layer w10: J2.3 1310,190 1675,190 v1(1725,240) 1725,346.52 v1(1610.76,460.76)
UART_GND: RF_UART.3 SIGPORT.3 | length 975.9
  Top Layer w25: SIGPORT.3 1278.44,3065 1798.92,3585.48 1798.92,3605.89 RF_UART.3
UART_RX: RF_UART.2 SIGPORT.5 | length 885.3
  Top Layer w25: SIGPORT.5 1329.23,3165 1749.7,3585.48 1749.7,3605.89 RF_UART.2
UART_Tx: RF_UART.1 SIGPORT.7 | length 792.2
  Top Layer w25: SIGPORT.7 1375.94,3265 1701.18,3590.24 RF_UART.1
USB_DM: R33.2 U14.32 | length 142.5
  Top Layer w10: U14.32 2479.01,777.99 2528.58,827.56 R33.2
USB_DP: R34.2 U14.33 | length 305.4
  Top Layer w10: v1@2352.67,797.68 U14.33
  Top Layer w15: v1@2352.67,797.68 v1(2350.78,795.79) 2372.05,795.79
  Bottom Layer w15: v1(2350.78,795.79) 2437.16,795.79 2528.58,704.37 R34.2
VCC: C2.1 C.1 R2.1 SERIAL.4@2845,1762.17 U1.7 U1.8 | length 2273.3
  Top Layer w10: U1.7 1532.56,670.17 1548.26,670.17 1570.5,692.41 U1.8 1570.5,719.65 1569.44,720.72 1539.28,720.72 1495,765 1495,830 1555,890 R2.1
  Top Layer w40: R2.1 1560,900 1560,985 1605,1030 ; v1(1622.25,1012.75) 1605,1030 ; SERIAL.4@2845,1762.17 2462.83,1380 1978.6,1380 1803.6,1205 1780,1205 1605,1030
  Bottom Layer w40: C.1 1605,895 ; v1(1622.25,1012.75) 1605,995.5 1605,895 ; C2.1 1605,895
pads on no net: CAN2.0 CAN2.1 CAN2.2 RF_UART.0 RF_UART.4 SERIAL.0 SERIAL.4@1576.18,183.43 SIGPORT.1 U1.1 U1.2 U1.9 U1.11 U1.13 U1.14 U1.15 U1.16 U1.17 U1.18 U1.19 U1.20 U1.21 U1.22 U1.23 U1.27 U14.2 U14.3 U14.4 U14.11 U14.12 U14.13 U14.14 U14.16 U14.17 U14.18 U14.19 U14.28 U14.29 U14.38 U14.39 U14.40

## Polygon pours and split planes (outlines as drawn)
CAN1_H on Bottom Layer "AMMO_GND_Poly" (solid, pour order 15): 1975,3790 1985,3780 1985,3495 2150,3330 2405,3330 2405,3325 2545,3185 2545,2550 2580,2515 2740,2515 2780,2555 2780,3340 2675,3340 2540,3475 2540,3785
AMMO_DC on Bottom Layer "AMMO_GND_Poly" (solid, pour order 11): 155,535 705,535 1060,890 1055,895 1055,1090 645,1500 155,1500
GNDG on Bottom Layer "BOTTOMPOLYGON" (solid, pour order 7): 2950,1135 2015,1135 1785,905 1785,335 1790,335 2015,110 2015,0.25 2610,0.25 2610,370 2695,455 2700,450 2950,450
no net on Bottom Layer "HeaterH" (solid, shelved, pour order 4): 2950,1100
no net on Bottom Layer "HeaterH" (solid, shelved, pour order 1): 2950,1275
CAN1_L on Top Layer "AMMO_GND_Poly" (solid, pour order 16): 2075,3620 2475,3620 2775,3320 2775,2540 2740,2505 2570,2505 2535,2540 2545,2550 2545,3190 2530,3190 2395,3325 2155,3325 2155,3330 1985,3500 1985,3600
GMB_DC on Top Layer "AMMO_GND_Poly" (solid, pour order 10): 890,885 925,920 1005,920 1065,860 1065,170 880,170 875,175 875,865
AMMO_GND on Top Layer "AMMO_GND_Poly" (solid, pour order 8): 360,1425 360,625 430,625 790,985 790,1060 425,1425
GMB_GND on Top Layer "AMMO_GND_Poly" (solid, pour order 9): 825,925 865,885 865,170 725,170 660,235 665,240 665,880 710,925
GNDG on Top Layer "TOPPOLYGON" (solid, pour order 6): 2950,1135 2015,1135 1820,940 1820,305 2015,110 2015,0.25 2610,0.25 2610,370 2695,455 2700,450 2950,450

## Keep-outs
Keep-Out Layer:
  the board outline again, w0.5

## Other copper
Bottom Layer:
  pour cut-out: 2073.5,1033.45 2161.16,1033.45 2185,1009.61 2185,986.58 2164.45,966.02 2079.42,966.02 2068.5,976.94 2068.5,1033.07 2071.24,1035.82

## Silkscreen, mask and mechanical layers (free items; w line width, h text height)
Top Overlay:
  lines w2: 2062.5,1135 2062.5,1235 2562.5,1235 2562.5,1135 2062.5,1135
  lines w40: 2044.23,1761.1 2151.04,2008.07 2192.08,1924.31 ; 2185.31,1761.6 2291.17,2012.28 2400,1760 ; 2253.24,1790.43 2293.49,1697.98 2399.41,1952.12
  text "METAINFANTRY" at 2310,2190 h24 r90
  text "M  E  T  A      R  O  B  O  T  I  C  S" at 2355,2190 h20.5 r90
  text "META_ROBOTICS" at 2028.89,1618.68 h30
  text "INFANTRY_PCB_GROUP V2.0 / RELEASE DATE JUN16,2021" at 2020,1500 h17
  text "AUTHOR_QUOKECOLA" at 2025,1464 h24
  text "DIO" at 2375,1200 h25
  text "CLK" at 2475,1200 h25
  text "5V0" at 2075,1150 h25
  text "3V3" at 2175,1150 h25
  text "GND" at 2275,1150 h25
  text "SWIM" at 2365,1150 h25
  text "NRS" at 2475,1150 h25
  text "F103 DIO CLK GND" at 2405,1090 h12.5
  text "F103 Rx Tx Gnd" at 2455,335 h12.5
  text "3V3 RTS RXD TXD DTR GND" at 845,120 h25
Mechanical 1:
  the board outline again, w0.5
